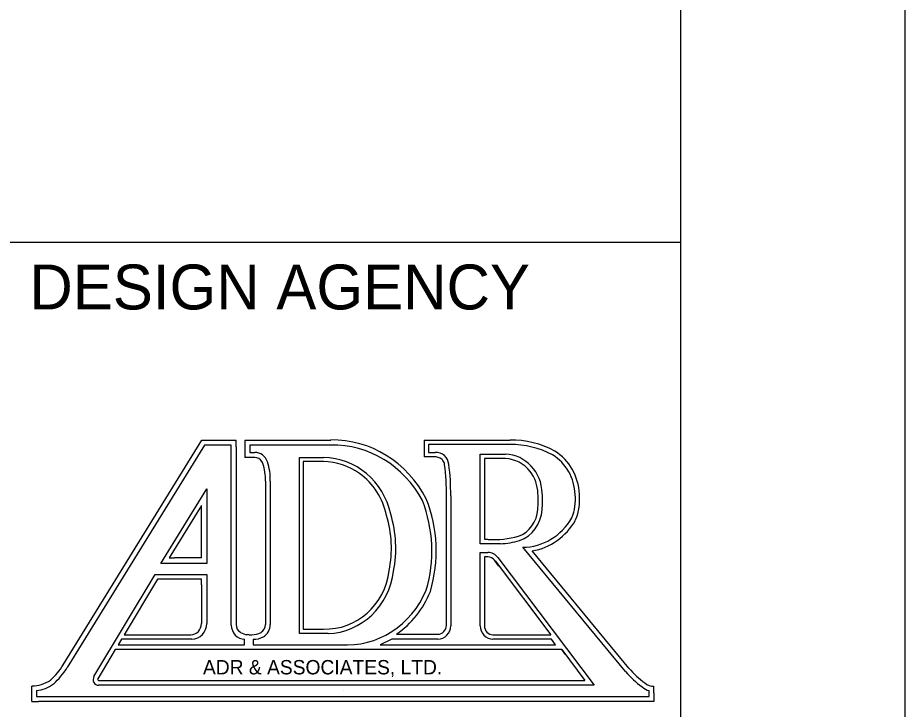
# Model space of a CAD drawing. Extents: x -8.6 to 34, y 0 to 22.
# Drawn here: x 32.024 to 34, y 3.459 to 5 of the extents above; entities that cross this region are included whole.
import ezdxf

# ---------------------------------------------------------------- set-up
doc = ezdxf.new("R2010")
doc.units = 0
for name, color, linetype in [('SH_Border', 7, 'Continuous'), ('SH_Cut_Line', 7, 'Continuous'), ('SH_Data', 7, 'Continuous')]:
    doc.layers.add(name, color=color, linetype=linetype)

msp = doc.modelspace()

# ---------------------------------------------------------------- linework, layer by layer
at = {"layer": 'SH_Border'}
msp.add_line((32, 4.5), (33.5, 4.5), dxfattribs=at)
msp.add_lwpolyline([(1.5, 21.5), (33.5, 21.5), (33.5, 0.5), (1.5, 0.5)], close=True, dxfattribs=at)
at = {"layer": 'SH_Cut_Line'}
msp.add_lwpolyline([(0, 0), (34, 0), (34, 22), (0, 22)], close=True, dxfattribs=at)
at = {"layer": 'SH_Data'}
for p, q in [((32.1254, 3.558), (32.4341, 4.0584)), ((32.4341, 4.0584), (32.5101, 4.0584)), ((32.5101, 4.0435), (32.5101, 4.0584)), ((32.53, 4.059), (32.53, 4.02)), ((32.53, 4.059), (32.721, 4.059)), ((32.929, 4.059), (32.929, 4.0215)), ((32.929, 4.059), (33.12, 4.059)), ((32.929, 4.059), (32.929, 4.0215)), ((32.929, 4.059), (33.12, 4.059)), ((32.5101, 4.0435), (32.5101, 3.6481)), ((32.5442, 4.02), (32.53, 4.02)), ((32.552, 4.02), (32.5442, 4.02)), ((32.7049, 4.011), (32.6598, 4.011)), ((32.6598, 4.011), (32.6598, 3.6379)), ((32.9432, 4.0215), (32.929, 4.0215)), ((32.9432, 4.0215), (32.929, 4.0215)), ((32.951, 4.0215), (32.9432, 4.0215)), ((32.5757, 3.9673), (32.5757, 3.6481)), ((32.9785, 3.6462), (32.9785, 3.9347)), ((32.4331, 3.9128), (32.3615, 3.7966)), ((32.4331, 3.8944), (32.4331, 3.9128)), ((32.4331, 3.7966), (32.4331, 3.8944)), ((32.3615, 3.7966), (32.3728, 3.7966)), ((32.4331, 3.7966), (32.3728, 3.7966)), ((33.3849, 3.5506), (33.1692, 3.8119)), ((33.0868, 3.7896), (33.2106, 3.6252)), ((32.3351, 3.7491), (32.2609, 3.6252)), ((32.4331, 3.7491), (32.3351, 3.7491)), ((32.4331, 3.7366), (32.4331, 3.7491)), ((32.4331, 3.7366), (32.4331, 3.6502)), ((32.6598, 3.6379), (32.6683, 3.6379)), ((32.6683, 3.6379), (32.7049, 3.6379)), ((32.2609, 3.6252), (32.2722, 3.6252)), ((32.2722, 3.6252), (32.4094, 3.6252)), ((32.5384, 3.6252), (32.5356, 3.6254)), ((32.5384, 3.6252), (32.5356, 3.6254)), ((32.5384, 3.6252), (32.5453, 3.6252)), ((32.8673, 3.6262), (32.9595, 3.6262)), ((33.0822, 3.6252), (33.2106, 3.6252)), ((33.2351, 3.5922), (33.2867, 3.5234)), ((32.2043, 3.5234), (32.2112, 3.5234)), ((32.2112, 3.5234), (33.2867, 3.5234)), ((32.0556, 3.4766), (32.0556, 3.5109)), ((32.75, 3.5), (32.75, 3.5)), ((33.4404, 3.496), (33.4404, 3.5102)), ((33.4404, 3.496), (33.4404, 3.4766)), ((32.0556, 3.4766), (32.0701, 3.4766)), ((33.4404, 3.4766), (32.0701, 3.4766))]:
    msp.add_line(p, q, dxfattribs=at)
for points in [[(32.4996, 3.6463), (32.4996, 4.0474), (32.4398, 4.0474), (32.1341, 3.552)], [(32.721, 4.0474), (32.541, 4.0474), (32.541, 4.0313), (32.552, 4.0313)], [(33.12, 4.049), (32.9385, 4.049), (32.9385, 4.0315), (32.9536, 4.0315)], [(32.6514, 3.6276), (32.6514, 4.02), (32.7049, 4.02)], [(33.0537, 4.0278), (33.1102, 4.0278)], [(33.0987, 3.8276), (33.0537, 3.8276), (33.0537, 4.0278)], [(33.11, 4.0178), (33.0632, 4.0178), (33.0632, 3.8384)], [(32.5864, 3.9673), (32.5864, 3.9668), (32.5864, 3.6481)], [(32.445, 3.7841), (32.3424, 3.7841), (32.445, 3.9504), (32.445, 3.7841)], [(32.988, 3.9346), (32.988, 3.6452)], [(33.3772, 3.5431), (33.1487, 3.82)], [(33.0932, 3.7972), (33.3075, 3.5126), (32.2038, 3.5126)], [(33.0537, 3.6452), (33.0537, 3.8086), (33.0709, 3.8086)], [(33.0709, 3.7986), (33.0632, 3.7986), (33.0632, 3.6452)], [(33.0954, 3.7782), (33.0857, 3.791)], [(32.1938, 3.5318), (32.3298, 3.7591), (32.445, 3.7591), (32.445, 3.6502)], [(32.715, 3.6276), (32.6514, 3.6276)], [(32.8673, 3.6262), (32.8894, 3.6262)], [(33.0822, 3.6252), (33.086, 3.6252)], [(32.4118, 3.6152), (32.2551, 3.6152), (32.2476, 3.6027), (32.5292, 3.6027), (32.5292, 3.6152)], [(32.5484, 3.6152), (32.5484, 3.6027), (32.7432, 3.6027)], [(32.9595, 3.6152), (32.857, 3.6152), (32.8311, 3.6027), (33.2217, 3.6027), (33.2123, 3.6152), (33.0822, 3.6152)], [(33.2426, 3.5822), (33.2351, 3.5922), (32.2412, 3.5922), (32.2022, 3.5272)], [(32.066, 3.5006), (32.066, 3.4876), (33.4299, 3.4876), (33.4299, 3.5006)]]:
    msp.add_lwpolyline(points, dxfattribs=at)
for centre, major_axis, start_param, end_param in [((32.7243, 3.8082), (0, 0.2509), 5.209873, 6.297313), ((33.1223, 3.8329), (0, 0.2261), 5.810103, 6.294452), ((33.1223, 3.8329), (0, 0.2261), 5.810103, 6.294452), ((32.552, 4), (0, 0.0313), 5.060756, 6.283185), ((32.726, 3.8081), (0, 0.2394), 5.218006, 6.305445), ((32.9522, 3.9897), (0, 0.0418), 5.696071, 6.248499), ((33.1224, 3.8335), (0, 0.2155), 5.814829, 6.29527), ((33.1638, 3.9336), (0, 0.1167), 4.753214, 5.755325), ((33.1638, 3.9336), (0, 0.1167), 4.753214, 5.755325), ((32.552, 4), (0, 0.02), 5.294753, 6.283185), ((32.552, 4), (0, 0.02), 5.060756, 5.294753), ((32.7039, 3.8572), (0, 0.1628), 4.938334, 6.276888), ((32.7028, 3.8574), (0, 0.1537), 5.684676, 6.268828), ((32.9522, 3.9897), (0, 0.0318), 5.717883, 6.322951), ((32.9551, 4.0016), (0, 0.0204), 5.34604, 5.529903), ((32.9551, 4.0016), (0, 0.0204), 4.827568, 5.34604), ((32.9551, 4.0016), (0, 0.0204), 4.827568, 5.34604), ((32.9551, 4.0016), (0, 0.0304), 4.832872, 5.561833), ((33.1063, 3.9378), (0, 0.08), 5.402738, 6.234422), ((33.1063, 3.9378), (0, 0.09), 4.740194, 6.23721), ((33.1638, 3.9336), (0, 0.1067), 4.750292, 5.755325), ((32.4775, 3.9716), (0, 0.1034), 4.671123, 5.060756), ((32.4775, 3.9716), (0, 0.1147), 4.675194, 5.060756), ((32.5748, 3.9427), (0, 0.425), 4.693619, 4.857063), ((32.5748, 3.9427), (0, 0.425), 4.693619, 4.857063), ((32.5748, 3.9427), (0, 0.435), 4.693836, 4.856756), ((32.7028, 3.8574), (0, 0.1537), 4.930275, 5.684676), ((33.1063, 3.9378), (0, 0.08), 4.740194, 5.402738), ((33.1063, 3.9378), (0, 0.08), 4.740194, 5.402738), ((33.0035, 3.9239), (0, 0.1889), 4.608112, 4.797709), ((33.0035, 3.9239), (0, 0.1889), 4.608112, 4.797709), ((33.0086, 3.9238), (0, 0.1936), 4.607961, 4.797558), ((33.166, 3.9266), (0, 0.1049), 4.309756, 4.818512), ((33.166, 3.9266), (0, 0.1149), 4.303317, 4.815541), ((33.166, 3.9266), (0, 0.1149), 4.303317, 4.815541), ((32.6675, 3.8117), (0, 0.2934), 4.410917, 5.105556), ((32.6675, 3.8117), (0, 0.3034), 4.410917, 5.105556), ((32.626, 3.8177), (0, 0.2524), 4.509144, 5.018206), ((33.1182, 3.9083), (0, -0.0672), 0.330696, 1.511334), ((33.1182, 3.9083), (0, -0.0672), 0.330696, 1.511334), ((33.1178, 3.9086), (0, -0.0777), 0.32607, 1.506707), ((32.6246, 3.8176), (0, 0.2435), 4.507644, 5.016706), ((33.1467, 3.957), (0, -0.1371), 0.015856, 1.021186), ((33.1467, 3.957), (0, -0.1471), 0.16231, 1.026165), ((33.1467, 3.957), (0, -0.1471), 0.16231, 1.026165), ((33.0851, 4.056), (0, -0.2188), 6.177822, 6.219099), ((33.0851, 4.056), (0, -0.2188), 6.219099, 6.545404), ((33.0851, 4.056), (0, -0.2188), 6.219099, 6.545404), ((33.0851, 4.056), (0, -0.2288), 0.06267, 0.262218), ((33.0709, 3.7786), (0, 0.03), 5.382662, 6.283185), ((33.0709, 3.7786), (0, 0.02), 5.382662, 6.283185), ((32.7099, 3.7877), (0, -0.1499), 6.247489, 7.723), ((32.7099, 3.7877), (0, -0.1602), 0.033392, 1.439815), ((32.7557, 3.807), (0, -0.2047), 6.218561, 7.439351), ((32.7556, 3.8048), (0, -0.2139), 0.582172, 1.170799), ((32.4094, 3.6502), (0, -0.025), 0, 1.570796), ((32.4118, 3.6502), (0, -0.035), 0, 1.570796), ((32.5292, 3.6463), (0, -0.0311), 4.712389, 6.28383), ((32.5291, 3.6481), (0, -0.02), 4.712389, 5.785309), ((32.5567, 3.6481), (0, -0.02), 0.497877, 1.570796), ((32.5567, 3.6481), (0, -0.0313), 0.497877, 1.570796), ((32.9595, 3.6462), (0, -0.02), 0, 1.570796), ((32.9595, 3.6452), (0, -0.03), 0, 1.570796), ((33.0822, 3.6452), (0, -0.03), 4.712389, 6.283185), ((33.0822, 3.6452), (0, -0.02), 4.712389, 6.283185), ((32.5401, 3.6695), (0, -0.0444), 5.785308, 6.174936), ((32.5456, 3.6695), (0, -0.0444), 6.276852, 6.781063), ((32.5506, 3.6599), (0, -0.0447), 6.230381, 6.780961), ((31.9988, 3.6451), (0, -0.1592), 0.707735, 0.991966), ((31.9988, 3.6451), (0, -0.1702), 0.704048, 0.991966), ((33.5477, 3.7078), (0, -0.2436), 5.454898, 5.668061), ((33.5477, 3.7078), (0, -0.2326), 5.454898, 5.66951), ((33.5477, 3.7078), (0, -0.2326), 5.454898, 5.66951), ((32.0559, 3.5887), (0, -0.0777), 6.278764, 6.875053), ((32.2038, 3.5251), (0, -0.0125), 4.150117, 6.283185), ((32.2043, 3.5259), (0, -0.0025), 4.150111, 6.283185), ((33.4405, 3.5437), (0, -0.0335), 5.601331, 6.280654), ((33.4405, 3.5437), (0, -0.0335), 5.601331, 6.280654), ((32.0559, 3.5887), (0, -0.0887), 0.120377, 0.599173), ((33.4405, 3.5437), (0, -0.0445), 5.61027, 6.031177)]:
    msp.add_ellipse(centre, major_axis=major_axis, ratio=0.95, start_param=start_param, end_param=end_param, dxfattribs=at)

# ---------------------------------------------------------------- texts
for s, height, p in [('DESIGN AGENCY', 0.1, (32.05, 4.35)), ('ADR & ASSOCIATES, LTD.', 0.032, (32.4365, 3.5368))]:
    msp.add_text(s, height=height, dxfattribs=at).set_placement(p)

doc.saveas('drawing.dxf')
